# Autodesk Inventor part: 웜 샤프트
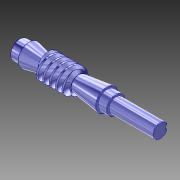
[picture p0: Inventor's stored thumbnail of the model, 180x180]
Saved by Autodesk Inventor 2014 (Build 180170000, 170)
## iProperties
Created: 2013-01
Part Number: 웜 샤프트
Material: 탄소강
Document SubType Name: Modeling
Designer: 한국산업디자인학원[gmhk.co.kr]
Categories: <?xml version="1.0" encoding="UTF-16"?> <MemberInstance><Categories><FamilyTemplate><FamilyTemplateParameter ValueType="xs:double" Id="1" ObjectReferenceKey="da
Density: 7.87 g/cm^3
Mass: 4106.37 g
Surface Area: 646.884 cm^2
Volume: 521.775 cm^3
Appearance: _시험-파란색 크롬
CustomPartVersion: 1
Author: 한국산업디자인학원[gmhk.co.kr]
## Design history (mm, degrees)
body "Solid1"
extrude "기본 본체" new body stored distance "d6" = 80 (= da_b); taper "d7" = 0 deg
chamfer "Chamfer1" distance "d8" = 4.00367 (= fd_cham1); stored, may be unused: second distance "d9" = 11 (= 0.5 x fd_cham2), angle "d47" = 45 deg
chamfer "Chamfer2" distance "d10" = 4.00367 (= fd_cham1); stored, may be unused: second distance "d11" = 11 (= 0.5 x fd_cham2), angle "d48" = 45 deg
sketch "톱니 스케치"
  geometry: L1 (0, 21.74)-(0, 10.96) reference; L2 (-60.834, 30.3)-(-56.721, 19); L3 (-53.235, 19)-(-49.122, 30.3); L4 (-50.535, 0)-(-37.455, 0) reference; L5 (-60.834, 30.3)-(-54.978, 30.3); L6 (-54.978, 30.3)-(-49.122, 30.3); L7 (-56.721, 19)-(-54.978, 19); L8 (-54.978, 19)-(-53.235, 19); L9 (-54.978, 25)-(-51.051, 25); L10 (-54.978, 30.3)-(-54.978, 19)
  constraints: 16 end point, 3 equal length, 3 parallel, 2 collinear, 2 point on line
  dimensions: "d24" = 110 deg angle of L7 L2 (computed from da_alfat); "d25" = 54.97787 distance from line of L1 L5.end (= fd_dist); "d26" = 3.92699 distance of L9.start L9.end (= 0.25 x da_px); "d27" = 19 distance between parallel lines of L4 L7 (= 0.5 x da_df); "d28" = 25 distance between parallel lines of L4 L9 (= 0.5 x da_d); "d29" = 30.3 distance between parallel lines of L4 L5 (= 0.505 x da_da)
feature "톱니" pitch "d30" = 31.41593 (computed from da_px, da_z); turns "d32" = 8 (= fd_n); dims "d31" = 10, "d33" = 0, angle "d34" = 90 deg, angle "d35" = 90 deg, "d36" = 0, "d37" = 0, "d70" = 10, "da_rightdir" = 0 [user parameter]
pattern_circular "톱니 패턴" dims angle "d46" = 360 deg, "da_rightdir" = 0 [user parameter]
feature "왼쪽 톱니" pitch "d62" = 31.41593 (computed from da_px, da_z); turns "d64" = 8 (= fd_n); dims "d63" = 10, "d65" = 0, angle "d66" = 90 deg, angle "d67" = 90 deg, "d68" = 0, "d69" = 0, "d76" = 10, "da_rightdir" = 0 [user parameter]
pattern_circular "왼쪽 톱니 패턴" dims angle "d73" = 360 deg, "da_rightdir" = 0 [user parameter]
sketch "스케치8"
  geometry: C1 r 18.99 at (0, 0); A1 r 19 centre (0, 0) between (9.02, 16.723) and (-3.823, 18.611) reference; A2 r 19 centre (0, 0) between (-3.823, 18.611) and (-9.02, -16.723) reference; A3 r 19 centre (0, 0) between (-9.02, -16.723) and (3.823, -18.611) reference; A4 r 19 centre (0, 0) between (3.823, -18.611) and (9.02, 16.723) reference; 1 further point
  constraints: 1 centre point, 1 coincident
  dimensions: "d87" = 0.01 radial gap between concentric circles of C1 A2
node "작업 평면10"
extrude "돌출2" join sketch "스케치8" distance "d88" = 1; taper "d89" = 0 deg
mirror "대칭1"
revolve "회전1" stored, may be unused: angle "d90" = 90 deg
chamfer "모따기3" distance "d91" = 1; stored, may be unused: second distance "d92" = 2, angle "d93" = 45 deg
node "작업 평면11"
sketch "스케치9"
  geometry: L1 (-54.5, -16.5)-(-54.5, 16.5) reference; L2 (-54.5, 5)-(-23.5, 5); L3 (-23.5, -5)-(-54.5, -5); A1 r 5 centre (-23.5, 0) between (-23.5, -5) and (-23.5, 5); 2 further points
  constraints: 4 end point, 2 perpendicular, 2 point on circle, 2 point on line, 2 tangent, 1 centre point, 1 horizontal alignment, 1 midpoint
  dimensions: "d94" = 10 distance between parallel lines of L3 L2; "d96" = 36 dimension on A1 L1
extrude "돌출3" cut sketch "스케치9" distance "d97" = 5; taper "d98" = 0 deg
node "기본 본체 스케치" dims "d5" = 60 (= da_da)
sketch "Sketch5"
  geometry: C1 r 30 at (0, 0) reference; C2 r 25 at (0, 0)
  constraints: 1 centre point, 1 coincident
  dimensions: "d59" = 50 diameter of C2 (= da_d)
body "Srf1"
sketch "스케치7"
  geometry: L1 (40, 18.611)-(40, -16.723) reference; L2 (40, 19)-(40, 16.723) reference; L3 (40, 18.611)-(40, 16.723) reference; L4 (40, -16.723)-(40, 18.611) reference; L5 (40, -18.611)-(40, -16.723) reference; L6 (40, 16.723)-(40, -18.611) reference; L7 (40, -16.723)-(40, -19) reference; L8 (41, 0)-(241, 0); L9 (110, 27.5)-(110, 22.5); L10 (110, 22.5)-(132, 22.5); L11 (132, 22.5)-(132, 17.5); L12 (132, 17.5)-(241, 17.5); L13 (241, 17.5)-(241, 0); L14 (127.9, 22.5)-(111.1, 22.5) reference; L15 (110, -41.4)-(110, 41.4) reference; L16 (-40, -16.723)-(-40, 18.611) reference; L17 (-41, 0)-(-105, 0); L18 (25.305, 19)-(-40, 19) reference; L19 (-82, 27.5)-(-82, 22.5); L20 (-82, 22.5)-(-105, 22.5); L21 (-105, 22.5)-(-105, 0); L22 (-82, 41.4)-(-82, -41.4) reference; L23 (41, 18.99)-(41, -18.99) reference; L24 (41, 0)-(41, 18.99); L25 (41, 18.99)-(110, 27.5); L26 (-41, 18.99)-(-41, -18.99) reference; L27 (-41, 0)-(-41, 18.99); L28 (-41, 18.99)-(-82, 27.5); 1 further point
  constraints: 30 end point, 7 collinear, 7 perpendicular, 2 midpoint, 1 horizontal, 1 horizontal alignment, 1 parallel, 1 point on line, 2 other
  dimensions: "d82" = 35 diameter of L12 L8; "d83" = 55 diameter of L9.start L8; "d84" = 22 distance of L9.end L10.end; "d85" = 200 distance of L8.start L8.end; "d86" = 64 distance of L17.start L17.end
node "투영된 루프1"
node "참조1"
node "참조2"
node "투영된 루프2"
feature "피치 지름" dims "d60" = 10, "d61" = 0
other parameters: "da_b" = 80 [user parameter; used in 3 equation terms], "da_df" = 38 [user parameter; used in 2 equation terms], "fd_cham2" = 22 (= da_da - da_df) [user parameter; used in 3 equation terms], "fd_cham1" = 4.00367 (= 0.181985 x fd_cham2) [user parameter; used in 2 equation terms], "da_d" = 50 [user parameter; used in 2 equation terms], "da_px" = 90 deg [user parameter; used in 5 equation terms], "fd_dist" = 54.97787 (computed from da_b, da_px) [user parameter; used in 1 equation term], "fd_n" = 8 (computed from da_b, da_px) [user parameter; used in 2 equation terms], "da_alfat" = 20 deg [user parameter; used in 1 equation term], "d12" = 110 deg (derived), "d14" = 3.1425 (derived), "d50" = 0, "d54" = 0, "d56" = 0, "d77" = 0, "d80" = 0
